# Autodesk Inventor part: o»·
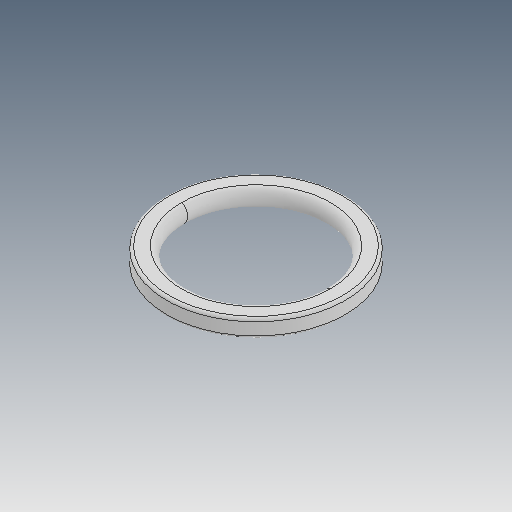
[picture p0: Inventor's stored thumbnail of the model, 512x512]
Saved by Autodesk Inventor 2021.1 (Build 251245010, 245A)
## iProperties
Created: 2013-04
Part Number: o»·
Material: Ogólny
Document SubType Name: Modeling
Designer: user
Density: 1 g/cm^3
Appearance: Domyślna
Author: user
Revision Number: ÈÎºÎ
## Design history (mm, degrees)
feature "Ô²½Ç1"
node "Bryła1"
